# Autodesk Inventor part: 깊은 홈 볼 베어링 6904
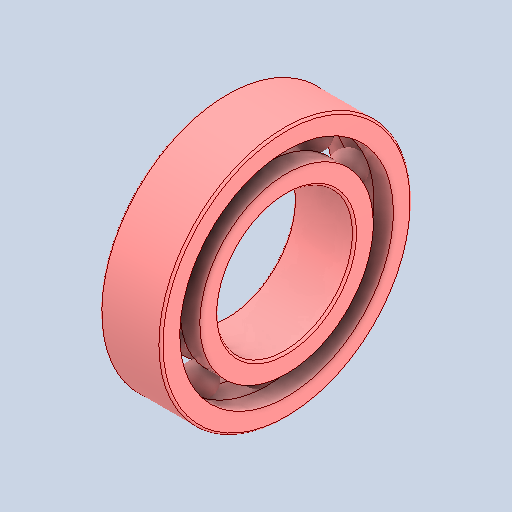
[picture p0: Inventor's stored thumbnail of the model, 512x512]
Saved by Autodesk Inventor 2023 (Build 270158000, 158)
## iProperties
Created: 2026-06
Part Number: 깊은 홈 볼 베어링 6904
Material: 강철, 연강
Description: 깊은 그루브 볼 베어링
Document SubType Name: Modeling
Designer: 4강의실
Density: 7.85 g/cm^3
Appearance: 기본값
Author: jhkim
Sending System: Autodesk Inventor 2027
Preprocessor: ST-DEVELOPER v20.1
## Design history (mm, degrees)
feature "Solid1"
feature "Solid1:1"
feature "Solid1:2"
feature "Solid1:3"
feature "Solid1:4"
feature "Solid1:5"
feature "Solid1:6"
feature "Solid1:7"
feature "Solid1:8"
feature "Solid1:9"
feature "Solid1:10"
feature "Solid1:11"
node "솔리드1"
node "솔리드2"
node "솔리드3"
node "솔리드4"
node "솔리드5"
node "솔리드6"
node "솔리드7"
node "솔리드8"
node "솔리드9"
node "솔리드10"
node "솔리드11"
node "솔리드12"
